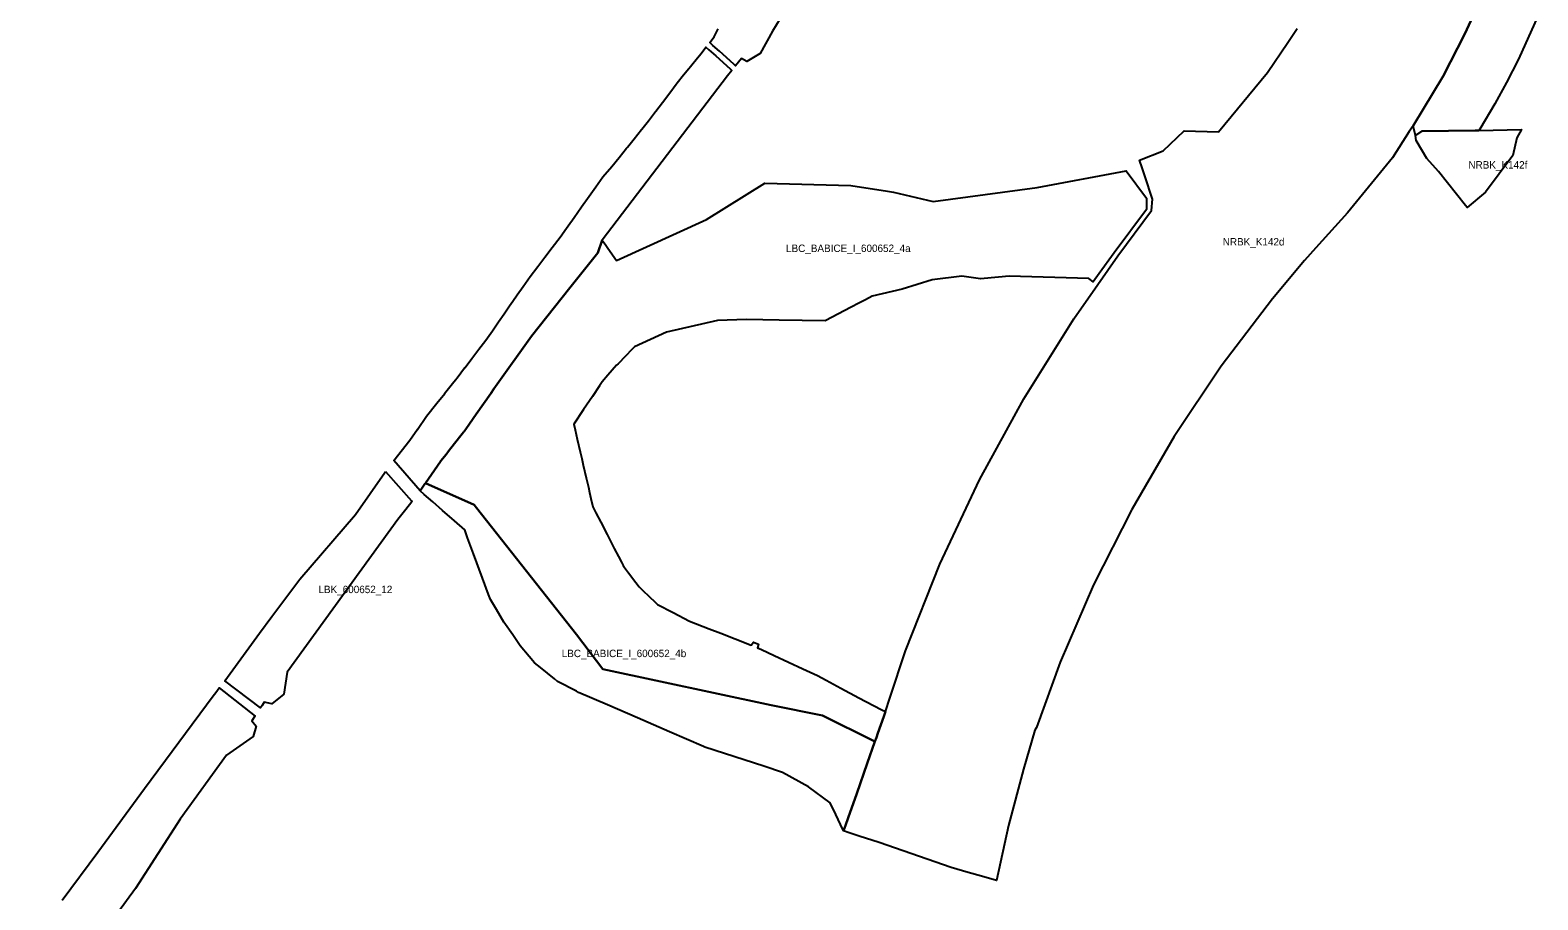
# Model space of a CAD drawing. Extents: x -537012 to -534434, y -1176840 to -1172739.
# Drawn here: x -535703 to -534687, y -1176244 to -1175657 of the extents above; entities that cross this region are included whole.
import ezdxf

# ---------------------------------------------------------------- set-up
doc = ezdxf.new("R2010")
doc.units = 0
for name, color, linetype in [('91230013', 7, 'Continuous'), ('91230023', 7, 'Continuous'), ('91270013', 7, 'Continuous'), ('91270023', 7, 'Continuous'), ('91280013', 7, 'Continuous')]:
    doc.layers.add(name, color=color, linetype=linetype)

msp = doc.modelspace()

# ---------------------------------------------------------------- linework, layer by layer
at = {"layer": '91230013'}
msp.add_lwpolyline([(-534729.02, -1175644.76), (-534735.93, -1175659.99), (-534750.52, -1175688.37), (-534770.72, -1175721.95), (-534773.44, -1175725.87), (-534784.66, -1175743.55), (-534814.99, -1175780.73), (-534836.42, -1175804.33), (-534844.09, -1175812.91), (-534865.58, -1175838.65), (-534900.16, -1175884.16), (-534931.82, -1175931.47), (-534960.54, -1175980.81), (-534986.37, -1176031.62), (-535008.76, -1176083.79), (-535024.61, -1176127.82), (-535025.82, -1176129.74), (-535033.52, -1176156.02), (-535043.53, -1176194.1), (-535051.68, -1176231.16), (-535061.71, -1176228.3), (-535070.7, -1176225.74), (-535082.15, -1176222.47), (-535130.73, -1176205.55), (-535144.25, -1176201.17), (-535151.07, -1176198.96), (-535154.82, -1176197.75), (-535153.49, -1176193.96), (-535151.7, -1176188.89), (-535145.91, -1176172.43), (-535138.79, -1176152.2), (-535133.61, -1176137.48), (-535132.61, -1176134.62), (-535131.63, -1176131.83), (-535127.65, -1176120.53), (-535126.42, -1176117.04), (-535123.51, -1176108.22), (-535112.98, -1176076.3), (-535089.97, -1176017.76), (-535063.2, -1175960.77), (-535033.24, -1175906.1), (-534999.62, -1175852.1), (-534983.44, -1175829.08), (-534969.88, -1175809.65), (-534947.07, -1175779.02), (-534946.52, -1175771.33), (-534951.76, -1175755.6), (-534953.52, -1175750.32), (-534955.25, -1175745.12), (-534939.36, -1175738.75), (-534925.24, -1175725.42), (-534902.05, -1175726.08), (-534868.94, -1175685.87), (-534855.33, -1175665.63), (-534848.96, -1175656.17)], dxfattribs=at)
msp.add_lwpolyline([(-534726.5, -1175725.15), (-534697.8, -1175724.5), (-534700.9, -1175730.1), (-534703.6, -1175742), (-534721.9, -1175766.7), (-534734.3, -1175777), (-534735.42, -1175775.61), (-534753.7, -1175752.8), (-534761.5, -1175743.9), (-534768.7, -1175731.9), (-534769.2, -1175728.4), (-534765, -1175725.6), (-534728.9, -1175725.2)], close=True, dxfattribs=at)
at = {"layer": '91230023'}
msp.add_lwpolyline([(-534686.68, -1175647.91), (-534699.7, -1175676.93), (-534707.75, -1175692.79), (-534715.69, -1175707.17), (-534725.88, -1175724.1), (-534726.5, -1175725.15), (-534728.9, -1175725.2), (-534765, -1175725.6), (-534769.2, -1175728.4), (-534770.72, -1175721.95), (-534750.52, -1175688.37), (-534735.93, -1175659.99), (-534729.02, -1175644.76)], dxfattribs=at)
at = {"layer": '91270013'}
msp.add_lwpolyline([(-535436.69, -1175963.12), (-535426.57, -1175948.45), (-535426.6, -1175948.42), (-535426.23, -1175947.95), (-535422.81, -1175943.62), (-535421.14, -1175941.51), (-535417.02, -1175936.3), (-535411.89, -1175929.81), (-535410.95, -1175928.62), (-535410.58, -1175928.09), (-535407.43, -1175923.6), (-535404.57, -1175919.51), (-535402.43, -1175916.46), (-535397.63, -1175909.6), (-535392.73, -1175902.6), (-535390.56, -1175899.49), (-535365.13, -1175863.92), (-535339.25, -1175831.19), (-535320.4, -1175807.66), (-535317.61, -1175799.04), (-535315.14, -1175802.53), (-535313.77, -1175804.46), (-535307.84, -1175812.81), (-535247.13, -1175785.26), (-535207.84, -1175760.65), (-535149.83, -1175762.25), (-535125.27, -1175766.1), (-535121.13, -1175766.75), (-535094.47, -1175772.94), (-535024.33, -1175763.57), (-534964.16, -1175752.21), (-534950.51, -1175770.73), (-534950.61, -1175778.33), (-534972.28, -1175807.68), (-534982.43, -1175821.7), (-534986.43, -1175827.21), (-534989.46, -1175824.91), (-535043.04, -1175823.29), (-535050.4, -1175823.98), (-535062.41, -1175825.11), (-535075.08, -1175823.28), (-535095.1, -1175825.79), (-535115.29, -1175832.21), (-535135.41, -1175836.85), (-535140.05, -1175839.3), (-535144.02, -1175841.39), (-535150.05, -1175844.57), (-535158.18, -1175848.85), (-535167.13, -1175853.57), (-535198.16, -1175853.04), (-535220.25, -1175852.67), (-535239.83, -1175853.35), (-535274.11, -1175861.12), (-535295.86, -1175871.17), (-535297.59, -1175872.96), (-535301.85, -1175877.35), (-535306.83, -1175882.48), (-535307.82, -1175883.5), (-535313.65, -1175890.19), (-535317.62, -1175894.74), (-535319.39, -1175897.37), (-535324.19, -1175904.5), (-535330.15, -1175913.36), (-535336.74, -1175923.15), (-535335.82, -1175927.11), (-535335.09, -1175930.24), (-535334.35, -1175933.46), (-535332.39, -1175941.92), (-535331.33, -1175946.51), (-535330.29, -1175951), (-535328.33, -1175959.48), (-535326.87, -1175965.76), (-535326.01, -1175969.46), (-535325.11, -1175973.34), (-535323.82, -1175978.94), (-535321.72, -1175983.04), (-535318.46, -1175989.39), (-535314.15, -1175997.77), (-535311.4, -1176003.13), (-535309.37, -1176007.08), (-535306.6, -1176012.48), (-535304.61, -1176016.37), (-535303.44, -1176018.64), (-535302.51, -1176019.89), (-535299.8, -1176023.52), (-535294.94, -1176030.03), (-535292.63, -1176033.12), (-535290.15, -1176035.46), (-535285.76, -1176039.61), (-535281.9, -1176043.26), (-535280.18, -1176044.88), (-535269.7, -1176050.34), (-535258.67, -1176056.08), (-535245.33, -1176061.3), (-535237.65, -1176064.31), (-535227.84, -1176068.14), (-535217.14, -1176072.33), (-535215.59, -1176070.35), (-535214.34, -1176070.85), (-535212.25, -1176071.68), (-535212.9, -1176074.1), (-535210.2, -1176075.34), (-535201.51, -1176079.34), (-535182.15, -1176088.27), (-535172.35, -1176092.79), (-535166.59, -1176095.9), (-535156.56, -1176101.32), (-535144.42, -1176107.88), (-535139.88, -1176110.34), (-535128.98, -1176115.95), (-535126.42, -1176117.04), (-535127.65, -1176120.53), (-535131.63, -1176131.83), (-535132.61, -1176134.62), (-535133.61, -1176137.48), (-535134.66, -1176136.96), (-535169.04, -1176119.86), (-535203.59, -1176112.91), (-535317.12, -1176088.61), (-535334.93, -1176065.14), (-535402.23, -1175979.7), (-535403.85, -1175977.64)], close=True, dxfattribs=at)
at = {"layer": '91270023'}
msp.add_lwpolyline([(-535436.69, -1175963.12), (-535403.85, -1175977.64), (-535402.23, -1175979.7), (-535334.93, -1176065.14), (-535317.12, -1176088.61), (-535203.59, -1176112.91), (-535169.04, -1176119.86), (-535134.66, -1176136.96), (-535133.61, -1176137.48), (-535138.79, -1176152.2), (-535145.91, -1176172.43), (-535151.7, -1176188.89), (-535153.49, -1176193.96), (-535154.82, -1176197.75), (-535156.89, -1176193.35), (-535160.02, -1176186.67), (-535163.75, -1176178.72), (-535178.52, -1176168.01), (-535196.01, -1176158.19), (-535208.54, -1176154.09), (-535248.23, -1176141.12), (-535249.25, -1176140.68), (-535272.14, -1176130.78), (-535293.74, -1176121.44), (-535314.01, -1176112.68), (-535333.44, -1176104.28), (-535334.8, -1176103.36), (-535347.64, -1176096.92), (-535349.8, -1176095.16), (-535359.23, -1176087.47), (-535363.21, -1176084.23), (-535366.75, -1176079.98), (-535372.8, -1176072.73), (-535377.89, -1176065.42), (-535383.95, -1176056.8), (-535388.88, -1176048.37), (-535392.88, -1176041.53), (-535394.14, -1176038.1), (-535398.17, -1176027.18), (-535404.21, -1176010.83), (-535408.25, -1175999.88), (-535410.18, -1175994.65), (-535417.16, -1175988.54), (-535425.27, -1175981.45), (-535431.84, -1175975.7), (-535437.53, -1175970.72), (-535440.26, -1175968.33), (-535437.02, -1175963.6), (-535436.86, -1175963.37)], close=True, dxfattribs=at)
at = {"layer": '91280013'}
for points in [[(-535195.2, -1175645.89), (-535202.74, -1175658.11), (-535210.95, -1175673.05), (-535220.03, -1175678.6), (-535223.72, -1175676.61), (-535227.6, -1175681.48), (-535228.86, -1175680.34), (-535238.5, -1175671.68), (-535242.98, -1175667.66), (-535245.05, -1175665.69), (-535242.02, -1175661.86), (-535239.38, -1175656.52)], [(-535681.71, -1176244.51), (-535657.63, -1176212.04), (-535626.09, -1176169.01), (-535579.75, -1176106.46), (-535578.1, -1176104.22), (-535575.75, -1176101.2), (-535551.61, -1176120.18), (-535551.69, -1176120.31), (-535553.82, -1176123.5), (-535550.75, -1176127.07), (-535552.89, -1176133.89), (-535570.8, -1176146.67), (-535602.1, -1176189.88), (-535632.19, -1176236.64), (-535703.24, -1176333.84)]]:
    msp.add_lwpolyline(points, dxfattribs=at)
for points in [[(-535436.69, -1175963.12), (-535436.86, -1175963.37), (-535437.02, -1175963.6), (-535440.26, -1175968.33), (-535457.98, -1175947.84), (-535447.21, -1175933.95), (-535442.17, -1175926.57), (-535442.12, -1175926.9), (-535435.91, -1175917.94), (-535429.03, -1175909.14), (-535423.68, -1175902.65), (-535423.74, -1175902.66), (-535423.87, -1175902.55), (-535418.41, -1175895.85), (-535416.43, -1175893.34), (-535415.4, -1175891.99), (-535410.29, -1175885.31), (-535410.04, -1175884.99), (-535405.39, -1175878.91), (-535400.66, -1175872.73), (-535395.99, -1175866.64), (-535391.55, -1175860.18), (-535387.49, -1175854.29), (-535383.68, -1175848.73), (-535379.57, -1175842.76), (-535379.37, -1175842.48), (-535375.28, -1175836.68), (-535374.77, -1175835.95), (-535370.76, -1175830.27), (-535366.06, -1175823.6), (-535360.98, -1175816.94), (-535356.16, -1175810.6), (-535351.21, -1175804.11), (-535345.85, -1175797.07), (-535341.62, -1175791.07), (-535340.52, -1175789.52), (-535336.42, -1175783.7), (-535331.39, -1175776.57), (-535326.37, -1175769.45), (-535321.9, -1175763.11), (-535317.02, -1175756.28), (-535311.1, -1175749.33), (-535306.01, -1175743.34), (-535301.07, -1175737.11), (-535300.55, -1175736.46), (-535295.93, -1175730.65), (-535291.03, -1175724.47), (-535290.74, -1175724.1), (-535286.29, -1175718.5), (-535281.64, -1175712.35), (-535281.34, -1175711.96), (-535276.9, -1175706.1), (-535272.03, -1175699.66), (-535267.58, -1175693.78), (-535266.92, -1175692.96), (-535262.63, -1175687.65), (-535259.12, -1175683.3), (-535257.99, -1175681.89), (-535253.34, -1175676.14), (-535250.88, -1175673.09), (-535247.58, -1175668.91), (-535245.6, -1175670.57), (-535240.91, -1175674.8), (-535231.26, -1175683.48), (-535230.05, -1175684.56), (-535232.96, -1175688.21), (-535317.61, -1175799.04), (-535320.4, -1175807.66), (-535339.25, -1175831.19), (-535365.13, -1175863.92), (-535390.56, -1175899.49), (-535392.73, -1175902.6), (-535397.63, -1175909.6), (-535402.43, -1175916.46), (-535404.57, -1175919.51), (-535407.43, -1175923.6), (-535410.58, -1175928.09), (-535410.95, -1175928.62), (-535411.89, -1175929.81), (-535417.02, -1175936.3), (-535421.14, -1175941.51), (-535422.81, -1175943.62), (-535426.23, -1175947.95), (-535426.6, -1175948.42), (-535426.57, -1175948.45)], [(-535463.75, -1175955.3), (-535446.09, -1175974.93), (-535445.68, -1175975.28), (-535446.65, -1175976.52), (-535451.76, -1175983.06), (-535455.23, -1175987.51), (-535530.06, -1176090.53), (-535532.28, -1176105.42), (-535540.24, -1176112.01), (-535545.43, -1176110.93), (-535546.85, -1176113.06), (-535547.96, -1176114.72), (-535572.04, -1176096.44), (-535570.1, -1176093.95), (-535548.55, -1176064.33), (-535540.25, -1176053.13), (-535521.49, -1176027.83), (-535483.92, -1175984.25), (-535464.13, -1175955.83)]]:
    msp.add_lwpolyline(points, close=True, dxfattribs=at)

# ---------------------------------------------------------------- texts
at = {"layer": '91230013'}
for s, rotation, p in [('NRBK_K142f', 0, (-534733.5, -1175750.79)), ('NRBK_K142d', 360, (-534899.15, -1175802.69))]:
    msp.add_text(s, height=5, rotation=rotation, dxfattribs=at).set_placement(p)
at = {"layer": '91270013'}
msp.add_text('LBC_BABICE_I_600652_4a', height=5, rotation=0, dxfattribs=at).set_placement((-535193.6, -1175807.08))
at = {"layer": '91270023'}
msp.add_text('LBC_BABICE_I_600652_4b', height=5, rotation=0, dxfattribs=at).set_placement((-535344.85, -1176080.44))
at = {"layer": '91280013'}
msp.add_text('LBK_600652_12', height=5, rotation=360, dxfattribs=at).set_placement((-535508.86, -1176037.26))

doc.saveas('drawing.dxf')
